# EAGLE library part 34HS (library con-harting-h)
CONNECTOR
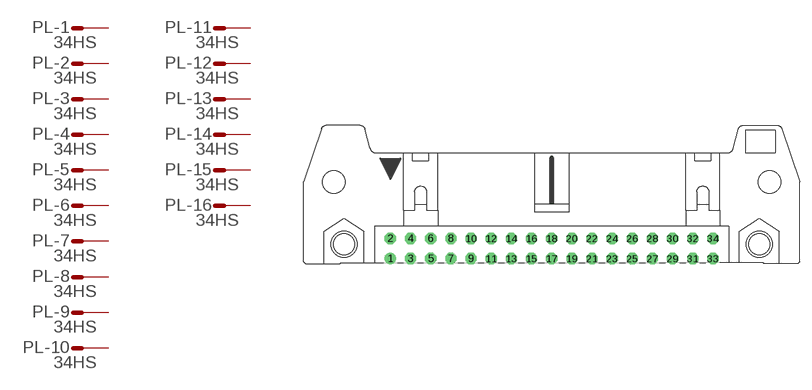
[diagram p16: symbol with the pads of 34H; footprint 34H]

Designator prefix PL; gates -1=M -2=M -3=M -4=M -5=M -6=M -7=M -8=M -9=M -10=M -11=M -12=M -13=M -14=M -15=M -16=M -17=M -18=M -19=M -20=M -21=M -22=M -23=M -24=M -25=M -26=M -27=M -28=M -29=M -30=M -31=M -32=M -33=M -34=M

## 34HS (OC_FARNELL: unknown; OC_NEWARK: unknown)  [34H]
1  -1:S  pas
2  -2:S  pas
3  -3:S  pas
4  -4:S  pas
5  -5:S  pas
6  -6:S  pas
7  -7:S  pas
8  -8:S  pas
9  -9:S  pas
10  -10:S  pas
11  -11:S  pas
12  -12:S  pas
13  -13:S  pas
14  -14:S  pas
15  -15:S  pas
16  -16:S  pas
17  -17:S  pas
18  -18:S  pas
19  -19:S  pas
20  -20:S  pas
21  -21:S  pas
22  -22:S  pas
23  -23:S  pas
24  -24:S  pas
25  -25:S  pas
26  -26:S  pas
27  -27:S  pas
28  -28:S  pas
29  -29:S  pas
30  -30:S  pas
31  -31:S  pas
32  -32:S  pas
33  -33:S  pas
34  -34:S  pas

## Footprint 34H (pad centres in mm)
CONNECTOR
drill 0.914 round: 1 -20.32,-1.27
drill 0.914 octagon: 2 -20.32,1.27; 3 -17.78,-1.27; 4 -17.78,1.27; 5 -15.24,-1.27; 6 -15.24,1.27; 7 -12.7,-1.27; 8 -12.7,1.27; 9 -10.16,-1.27; 10 -10.16,1.27; 11 -7.62,-1.27; 12 -7.62,1.27; 13 -5.08,-1.27; 14 -5.08,1.27; 15 -2.54,-1.27; 16 -2.54,1.27; 17 0,-1.27; 18 0,1.27; 19 2.54,-1.27; 20 2.54,1.27; 21 5.08,-1.27; 22 5.08,1.27; 23 7.62,-1.27; 24 7.62,1.27; 25 10.16,-1.27; 26 10.16,1.27; 27 12.7,-1.27; 28 12.7,1.27; 29 15.24,-1.27; 30 15.24,1.27; 31 17.78,-1.27; 32 17.78,1.27; 33 20.32,-1.27; 34 20.32,1.27
hole 3.302 at -26.162,0.533
hole 3.302 at 26.162,0.533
